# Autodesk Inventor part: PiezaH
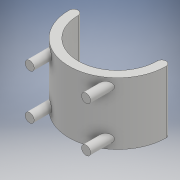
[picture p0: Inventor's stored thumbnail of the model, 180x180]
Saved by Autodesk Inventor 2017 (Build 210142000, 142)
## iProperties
Part Number: PiezaH
Material: Genérico
Document SubType Name: Modeling
Designer: Jaime
Density: 1 g/cm^3
Appearance: Valor por defecto
Mass: 60.3142 g
Surface Area: 187.002 cm^2
Volume: 60.3142 cm^3
Author: Jaime
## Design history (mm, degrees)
sketch "Boceto1"
  geometry: A1 r 35 centre (0, 0) between (-35, 0) and (35, 0); A2 r 4 centre (-39, 0) between (-35, 0) and (-43, 0); A3 r 4 centre (39, 0) between (43, 0) and (35, 0); A4 r 43 centre (0, 0) between (-43, 0) and (43, 0); 1 further point
  constraints: 8 point on circle, 4 centre point, 4 tangent, 2 coincident, 1 horizontal alignment
  dimensions: "d0" = 70 distance of A1.end A1.start; "d1" = 35 radius of A1; "d2" = 8 diameter of A2; "d3" = 8 diameter of A3; "d5" = 43 radius of A4
extrude "Extrusión1" new body sketch "Boceto1" distance "d6" = 55; taper "d7" = 0 deg
node "Punto de trabajo1"
node "Plano de trabajo1"
sketch "Boceto2"
  geometry: L1 (-43, 0)-(43, 0) reference; C1 r 4 at (25, 8); C2 r 4 at (-25, 8); C3 r 4 at (-25, 48); C4 r 4 at (25, 48); 1 further point
  constraints: 4 centre point, 2 horizontal alignment, 2 vertical alignment
  dimensions: "d8" = 8 diameter of C1; "d9" = 8 diameter of C2; "d10" = 8 diameter of C3; "d11" = 8 diameter of C4; "d12" = 50 distance of C2.centre C1.centre; "d13" = 40 distance of C3.centre C2.centre; "d14" = 8 distance from line of C2.centre L1; "d15" = 25 horizontal distance of point (0, 0) C2.centre
extrude "Extrusión2" join sketch "Boceto2" stored distance "d16" = 50; taper "d17" = 0 deg
extrude "Extrusión3" join sketch "Boceto2" distance "d18" = 10; taper "d19" = 0 deg
node "Sólido1"
